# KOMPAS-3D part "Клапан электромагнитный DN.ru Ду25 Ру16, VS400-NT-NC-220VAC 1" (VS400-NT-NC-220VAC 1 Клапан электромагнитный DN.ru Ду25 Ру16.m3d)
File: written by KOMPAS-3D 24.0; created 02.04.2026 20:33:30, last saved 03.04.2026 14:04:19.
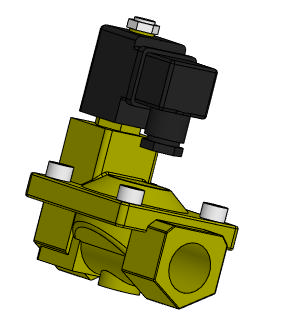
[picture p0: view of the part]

Document properties: Автор: artio; Полное имя файла: C:\Users\artio\OneDrive\Рабочий стол\Клапан электромагнитный DN.ru VS4x-xT-NC-x\VS400-NT-NC\VS400-NT-NC-220VAC 1 Клапан электромагнитный DN.ru Ду25 Ру16.m3d

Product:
- Body: Тело 1  | qty 1
    Масса: 1.76797
- Part/product: Клапан электромагнитный DN.ru Ду25 Ру16  | designation VS400-NT-NC-220VAC 1
    Масса: 1.524
    Раздел спецификации: Прочие изделия
    Примечание: D130-04663
    additional columns: ef56311e-7521-43dc-8291-0e6108b3d81d; VS400-ET-NC-220VAC 1; artio; c; Шероховатость не задана; Да

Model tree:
1. Операция без истории:1

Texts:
  VS400-NT-NC-220VAC 1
